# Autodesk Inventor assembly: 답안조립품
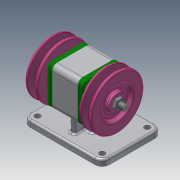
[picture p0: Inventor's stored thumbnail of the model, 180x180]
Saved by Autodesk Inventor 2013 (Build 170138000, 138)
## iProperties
Created: 2020-11
Part Number: 답안조립품
Document SubType Name: Assembly
Designer: 19
Author: 19
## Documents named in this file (10)
- C:\Users\user\Desktop\701106V1012\답안조립품.iam
- C:\Users\user\Desktop\701106V1012\본체.ipt
- C:\Users\user\Desktop\701106V1012\V-벨트풀리.ipt
- C:\Users\user\Desktop\701106V1012\너트 M10x1.ipt
- C:\Users\user\Desktop\701106V1012\베어링 6004.ipt
- C:\Users\user\Desktop\701106V1012\볼트 M4.ipt
- C:\Users\user\Desktop\701106V1012\오일 실 17 30 5.ipt
- C:\Users\user\Desktop\701106V1012\축.ipt
- C:\Users\user\Desktop\701106V1012\커버.ipt
- C:\Users\user\Desktop\701106V1012\키 5 x 5 x 12.ipt
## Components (2 placed, 1 different names)
1. V-벨트풀리:1
2. V-벨트풀리:2
